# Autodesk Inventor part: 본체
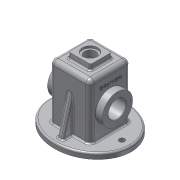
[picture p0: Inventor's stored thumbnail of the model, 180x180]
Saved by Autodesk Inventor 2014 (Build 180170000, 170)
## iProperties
Created: 2017-07
Part Number: 본체
Material: Aluminum 6061
Document SubType Name: Modeling
Designer: user
Density: 2.71 g/cm^3
Appearance: Aluminum - Flat
Mass: 887.783 g
Surface Area: 995.339 cm^2
Volume: 327.595 cm^3
Author: user
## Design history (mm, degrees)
sketch "Sketch1" dims "d0" = 75, "d1" = 65
  geometry: 2 further points; 1 other entity
  constraints: 1 coincident, 2 other
extrude "Extrusion1" new body sketch "Sketch1" distance "d2" = 10; taper "d3" = 0 deg
sketch "Sketch2"
  geometry: L1 (37, -37)-(-37, -37); L2 (-37, -37)-(-37, 37); L3 (-37, 37)-(37, 37); L4 (37, 37)-(37, -37); L5 (37, -37)-(-37, 37); L6 (-37, -37)-(37, 37); 1 further point; 1 other entity
  constraints: 12 end point, 2 midpoint, 2 parallel, 1 horizontal, 1 perpendicular, 1 other
  dimensions: "d4" = 74 distance of L2.end L3.end; "d5" = 74 distance of L1.end L2.end
extrude "Extrusion2" join sketch "Sketch2" distance "d6" = 100; taper "d7" = 0 deg
sketch "Sketch3"
  geometry: L1 (37, 77.177)-(55, 10); L2 (37, 10)-(37, 110) reference; L3 (65, 10)-(-65, 10) reference; L4 (37, 77.177)-(37, 10); L5 (37, 10)-(55, 10); L6 (65, 10)-(65, 79.466); 1 further point
  constraints: 8 end point, 1 perpendicular
  dimensions: "d8" = 0 distance from line of L2 L1.start; "d9" = 0 distance from line of L3 L1.end; "d10" = 10 distance of L3.start L1.end; "d11" = 15 deg angle of L6 L1; "d12" = 69.46563 distance from line of L6.end L3
extrude "Extrusion3" join sketch "Sketch3" stored distance "d13" = 10; taper "d14" = 0 deg
mirror "Mirror1"
sketch "Sketch4"
  geometry: L1 (10, -28)-(10, 102) reference; C1 r 27.5 at (-45, 37); 1 further point
  constraints: 1 centre point
  dimensions: "d15" = 55 distance from line of L1 C1.centre; "d16" = 55 diameter of C1
extrude "Extrusion4" join sketch "Sketch4" distance "d17" = 13; taper "d18" = 0 deg
sketch "Sketch5"
  geometry: C1 r 27.5 at (0, 0) reference; C2 r 16 at (0, 0); 1 further point
  constraints: 1 centre point, 1 coincident
  dimensions: "d19" = 32 diameter of C2
extrude "Extrusion5" cut sketch "Sketch5" stored distance "d20" = 13; taper "d21" = 0 deg
sketch "Sketch6" dims "d22" = 45
  geometry: L1 (-1.635, 0)-(-22.5, 0); C1 r 27.5 at (0, 0) reference; 3 further points
  constraints: 2 coincident, 2 end point, 1 horizontal, 1 horizontal alignment, 2 other
hole "Hole1" sketch "Sketch6" at (-22.5, 0) diameter "d23" = 3.242; stored, may be unused: countersink angle "d27" = 90 deg, drill point angle "d29" = 118 deg; dims "d24" = 8, "d25" = 4, "d26" = 2, "d28" = 10
pattern_circular "Circular Pattern1" dims angle "d31" = 360 deg
mirror "Mirror2"
sketch "Sketch7"
  geometry: L1 (20, -20)-(-20, -20); L2 (-20, -20)-(-20, 20); L3 (-20, 20)-(20, 20); L4 (20, 20)-(20, -20); L5 (20, -20)-(-20, 20); L6 (-20, -20)-(20, 20); 1 further point
  constraints: 12 end point, 2 midpoint, 2 parallel, 1 horizontal, 1 perpendicular
  dimensions: "d33" = 40 distance of L2.end L3.end; "d34" = 40 distance of L1.end L2.end
extrude "Extrusion6" join sketch "Sketch7" distance "d35" = 10; taper "d36" = 0 deg
sketch "Sketch8"
  geometry: L1 (32, -32)-(-32, -32); L2 (-32, -32)-(-32, 32); L3 (-32, 32)-(32, 32); L4 (32, 32)-(32, -32); L5 (32, -32)-(-32, 32); L6 (-32, -32)-(32, 32); 1 further point; 1 other entity
  constraints: 12 end point, 2 midpoint, 2 parallel, 1 horizontal, 1 perpendicular, 1 other
  dimensions: "d37" = 64 distance of L2.end L3.end; "d38" = 64 distance of L1.end L2.end
extrude "Extrusion7" cut sketch "Sketch8" distance "d39" = 105; taper "d40" = 0 deg
sketch "Sketch9"
  geometry: L1 (50, 55)-(-50, 55); L2 (50, 71)-(50, 39) reference; L3 (-50, 39)-(-50, 71) reference; L4 (-25, 71)-(-25, 75.5); L5 (-32, 0)-(-32, 105) reference; L6 (-25, 75.5)-(-32, 82.5); L7 (-25, 71)-(-32, 71); L8 (-32, 71)-(-32, 82.5); L9 (0, 55)-(0, 87.906); L10 (25, 71)-(25, 75.5); L11 (32, 0)-(32, 105); L12 (25, 75.5)-(32, 82.5); L13 (25, 71)-(32, 71); L14 (32, 71)-(32, 82.5); 2 further points
  constraints: 22 end point, 6 symmetric about line, 4 point on line, 2 midpoint, 2 parallel, 1 coincident, 1 collinear, 1 horizontal, 1 perpendicular
  dimensions: "d41" = 0 distance from line of L1.start L2; "d42" = 0 distance from line of L3 L1.end; "d43" = 7 distance between parallel lines of L4 L5; "d44" = 135 deg angle of L5 L6; "d45" = 55 diameter of L6.end L1; "d46" = 32 diameter of L7 L1; "d47" = 16.90632 distance from line of L9.end L7
revolve "Revolution1" sketch "Sketch9" stored, may be unused: angle "d48" = 90 deg
sketch "Sketch10"
  geometry: C1 r 14 at (0, 0); 1 further point
  constraints: 1 centre point, 1 coincident
  dimensions: "d49" = 28 diameter of C1
extrude "Extrusion8" cut sketch "Sketch10" distance "d50" = 4; taper "d51" = 0 deg
sketch "Sketch11"
  geometry: C1 r 14 at (0, 0) reference; C2 r 10.5 at (0, 0)
  constraints: 1 centre point, 1 coincident
  dimensions: "d52" = 21 diameter of C2
extrude "Extrusion9" cut sketch "Sketch11" stored distance "d53" = 4; taper "d54" = 0 deg
sketch "Sketch12"
  geometry: L1 (37, 37)-(37, -37) reference; C1 r 5 at (-58, 0); C2 r 5 at (58, 0); 1 further point; 1 other entity
  constraints: 2 centre point, 1 horizontal alignment, 1 other
  dimensions: "d55" = 10 diameter of C2; "d56" = 10 diameter of C1; "d57" = 58 distance of point (0, 0) C1.centre; "d58" = 116 distance of C2.centre C1.centre; "d59" = 21 distance from line of C2.centre L1
extrude "Extrusion10" cut sketch "Sketch12" stored distance "d60" = 4; taper "d61" = 0 deg
fillet "Fillet1" dims "d62" = 3
fillet "Fillet2" dims "d63" = 3
fillet "Fillet3" dims "d64" = 8
fillet "Fillet4" dims "d65" = 8
fillet "Fillet7" dims "d68" = 0.5
fillet "Fillet8" dims "d69" = 0.5
fillet "Fillet9" dims "d70" = 3
fillet "Fillet10" dims "d71" = 3
sketch "Sketch13"
  geometry: L1 (-10, 0)-(-10, 40) reference; L2 (0, 0)-(-10, 0) reference; L3 (0, 0)-(-10, 0.875); L4 (8, -17)-(97, -17) reference; L5 (0, 40)-(-10, 39.125); L6 (97, 57)-(8, 57) reference; L7 (0, 0)-(-10, 0); L8 (-10, 0)-(-10, 0.875); L9 (0, 40)-(-10, 40); L10 (-10, 40)-(-10, 39.125); 1 further point
  constraints: 12 end point, 3 point on line, 2 collinear, 2 perpendicular
  dimensions: "d72" = 5 deg angle of L3 L4; "d73" = 5 deg angle of L6 L5
extrude "Extrusion11" cut sketch "Sketch13" stored distance "d74" = 4; taper "d75" = 0 deg
chamfer "Chamfer1" distance "d76" = 1; stored, may be unused: second distance "d77" = 2, angle "d78" = 45 deg
fillet "Fillet11" dims "d79" = 3
fillet "Fillet12" dims "d80" = 3
workplane "Work Plane1"
sketch "Sketch14"
  geometry: L1 (-18, 12.886)-(-18, 45.114) reference; C1 r 16 at (47, 29) reference; 2 further points
  constraints: 1 other
  dimensions: "d82" = 30 distance from line of L1 point (12, 29); "d83" = 0 vertical distance of point (12, 29) C1.centre
emboss "Emboss1" sketch "Sketch14" dims "d0" = 75, "d1" = 65, "d8" = 0, "d9" = 0, "d10" = 10, "d11" = 15 deg, "d12" = 69.46563, "d84" = 0.5, "d85" = 0
fillet "Fillet13" dims "d86" = 3
fillet "Fillet14" dims "d87" = 3
body "Solid1"
other parameters: "d81" = 77
